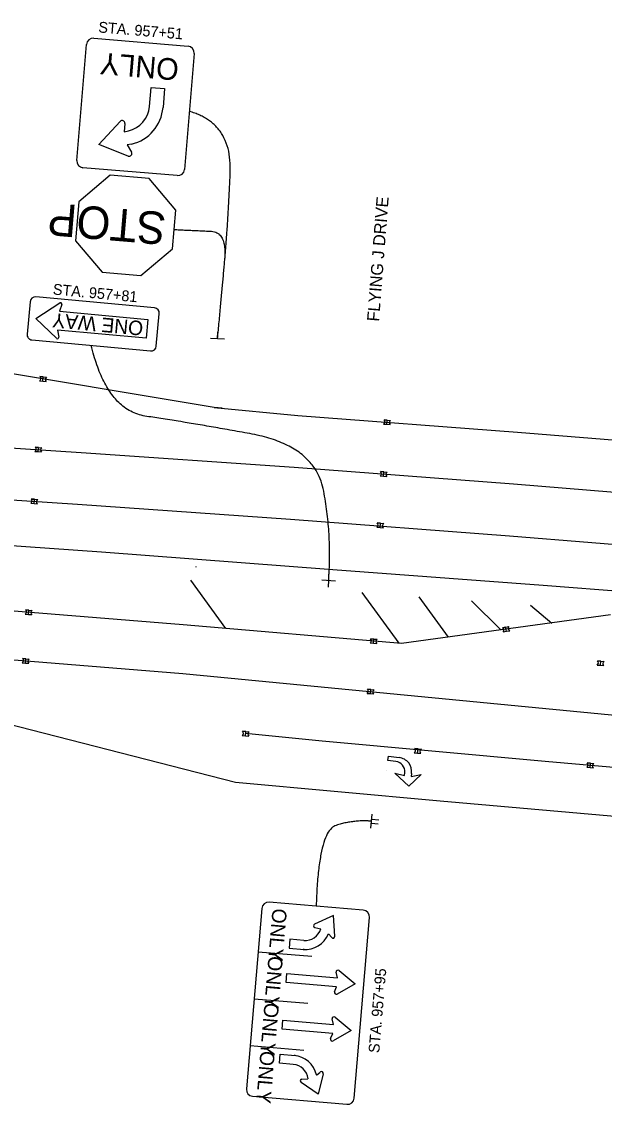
# Model space of a CAD drawing. Extents: x 1847379 to 1850904, y 217032 to 220169.
# Drawn here: x 1849844.7 to 1849979.4, y 218660.5 to 218910.6 of the extents above; entities that cross this region are included whole.
import ezdxf

# ---------------------------------------------------------------- set-up
doc = ezdxf.new("R2010")
doc.units = 0
for name, color, linetype in [('PM_P_Cells', 7, 'Continuous'), ('PM_P_Channelizing_Line', 7, 'Continuous'), ('PM_P_CL_Double_Solid', 7, 'Continuous'), ('PM_P_Edge_Line', 7, 'Continuous'), ('PM_P_Lane_Line', 7, 'Continuous'), ('PM_P_Transverse_Line', 7, 'Continuous'), ('SN_X_Public', 7, 'Continuous'), ('SN_X_Text', 7, 'Continuous')]:
    doc.layers.add(name, color=color, linetype=linetype)

msp = doc.modelspace()

# ---------------------------------------------------------------- linework, layer by layer
at = {"layer": 'PM_P_Cells'}
for p, q in [((1849849.72, 218828.51), (1849848.95, 218828.58)), ((1849848.95, 218828.58), (1849849.72, 218828.51)), ((1849849.63, 218827.54), (1849849.72, 218828.51)), ((1849849.72, 218828.51), (1849850.49, 218828.45)), ((1849848.87, 218827.61), (1849849.63, 218827.54)), ((1849848.87, 218827.61), (1849849.63, 218827.54)), ((1849849.63, 218827.54), (1849850.4, 218827.47)), ((1849929.23, 218818.54), (1849928.47, 218818.61)), ((1849928.47, 218818.61), (1849929.23, 218818.54)), ((1849929.14, 218817.57), (1849929.23, 218818.54)), ((1849929.23, 218818.54), (1849930, 218818.47)), ((1849928.38, 218817.64), (1849929.14, 218817.57)), ((1849928.38, 218817.64), (1849929.14, 218817.57)), ((1849929.14, 218817.57), (1849929.91, 218817.5)), ((1849847.78, 218811.33), (1849848.55, 218811.26)), ((1849847.78, 218811.33), (1849848.55, 218811.26)), ((1849848.63, 218812.23), (1849847.87, 218812.3)), ((1849847.87, 218812.3), (1849848.63, 218812.23)), ((1849848.55, 218811.26), (1849848.63, 218812.23)), ((1849848.55, 218811.26), (1849849.31, 218811.19)), ((1849848.63, 218812.23), (1849849.4, 218812.16)), ((1849927.58, 218805.66), (1849928.35, 218805.6)), ((1849927.58, 218805.66), (1849928.35, 218805.6)), ((1849928.43, 218806.57), (1849927.67, 218806.64)), ((1849927.67, 218806.64), (1849928.43, 218806.57)), ((1849928.35, 218805.6), (1849928.43, 218806.57)), ((1849928.43, 218806.57), (1849929.2, 218806.5)), ((1849928.35, 218805.6), (1849929.11, 218805.53)), ((1849846.81, 218799.34), (1849847.57, 218799.27)), ((1849846.81, 218799.34), (1849847.57, 218799.27)), ((1849847.66, 218800.25), (1849846.89, 218800.32)), ((1849846.89, 218800.32), (1849847.66, 218800.25)), ((1849847.57, 218799.27), (1849847.66, 218800.25)), ((1849847.57, 218799.27), (1849848.34, 218799.21)), ((1849847.66, 218800.25), (1849848.43, 218800.18)), ((1849926.79, 218793.84), (1849927.56, 218793.77)), ((1849926.79, 218793.84), (1849927.56, 218793.77)), ((1849927.64, 218794.74), (1849926.88, 218794.81)), ((1849926.88, 218794.81), (1849927.64, 218794.74)), ((1849927.56, 218793.77), (1849927.64, 218794.74)), ((1849927.56, 218793.77), (1849928.32, 218793.7)), ((1849927.64, 218794.74), (1849928.41, 218794.67)), ((1849845.53, 218773.74), (1849846.29, 218773.68)), ((1849845.53, 218773.74), (1849846.29, 218773.68)), ((1849846.38, 218774.65), (1849845.61, 218774.72)), ((1849845.61, 218774.72), (1849846.38, 218774.65)), ((1849846.29, 218773.68), (1849846.38, 218774.65)), ((1849846.29, 218773.68), (1849847.06, 218773.61)), ((1849846.38, 218774.65), (1849847.15, 218774.58)), ((1849956.59, 218770.72), (1849955.84, 218770.57)), ((1849955.84, 218770.57), (1849956.59, 218770.72)), ((1849956.59, 218770.72), (1849957.35, 218770.87)), ((1849956.78, 218769.76), (1849956.59, 218770.72)), ((1849956.03, 218769.61), (1849956.78, 218769.76)), ((1849956.03, 218769.61), (1849956.78, 218769.76)), ((1849956.78, 218769.76), (1849957.54, 218769.91)), ((1849925.27, 218767.08), (1849926.04, 218767.01)), ((1849925.27, 218767.08), (1849926.04, 218767.01)), ((1849926.12, 218767.98), (1849925.36, 218768.05)), ((1849925.36, 218768.05), (1849926.12, 218767.98)), ((1849926.04, 218767.01), (1849926.12, 218767.98)), ((1849926.04, 218767.01), (1849926.8, 218766.94)), ((1849926.12, 218767.98), (1849926.89, 218767.91)), ((1849845.69, 218763.41), (1849844.92, 218763.48)), ((1849844.92, 218763.48), (1849845.69, 218763.41)), ((1849845.6, 218762.44), (1849845.69, 218763.41)), ((1849845.69, 218763.41), (1849846.46, 218763.34)), ((1849844.84, 218762.51), (1849845.6, 218762.44)), ((1849844.84, 218762.51), (1849845.6, 218762.44)), ((1849845.6, 218762.44), (1849846.37, 218762.37)), ((1849977.71, 218761.98), (1849978.48, 218761.91)), ((1849977.71, 218761.98), (1849978.48, 218761.91)), ((1849978.57, 218762.88), (1849977.8, 218762.95)), ((1849977.8, 218762.95), (1849978.57, 218762.88)), ((1849978.48, 218761.91), (1849978.57, 218762.88)), ((1849978.48, 218761.91), (1849979.25, 218761.84)), ((1849978.57, 218762.88), (1849979.34, 218762.81)), ((1849925.41, 218756.34), (1849924.64, 218756.41)), ((1849924.64, 218756.41), (1849925.41, 218756.34)), ((1849925.32, 218755.37), (1849925.41, 218756.34)), ((1849925.41, 218756.34), (1849926.18, 218756.27)), ((1849924.55, 218755.43), (1849925.32, 218755.37)), ((1849924.55, 218755.43), (1849925.32, 218755.37)), ((1849925.32, 218755.37), (1849926.09, 218755.3)), ((1849895.67, 218745.72), (1849896.44, 218745.65)), ((1849895.67, 218745.72), (1849896.44, 218745.65)), ((1849896.53, 218746.62), (1849895.76, 218746.69)), ((1849895.76, 218746.69), (1849896.53, 218746.62)), ((1849896.44, 218745.65), (1849896.53, 218746.62)), ((1849896.44, 218745.65), (1849897.21, 218745.58)), ((1849896.53, 218746.62), (1849897.3, 218746.55)), ((1849929.38, 218739.89), (1849929.5, 218740.89)), ((1849929.5, 218740.89), (1849931.96, 218740.6)), ((1849935.47, 218741.72), (1849936.24, 218741.65)), ((1849935.47, 218741.72), (1849936.24, 218741.65)), ((1849936.33, 218742.62), (1849935.56, 218742.69)), ((1849935.56, 218742.69), (1849936.33, 218742.62)), ((1849936.24, 218741.65), (1849936.33, 218742.62)), ((1849936.24, 218741.65), (1849937.01, 218741.58)), ((1849936.33, 218742.62), (1849937.1, 218742.55)), ((1849931.24, 218739.68), (1849929.38, 218739.89)), ((1849975.34, 218738.39), (1849976.11, 218738.32)), ((1849975.34, 218738.39), (1849976.11, 218738.32)), ((1849976.19, 218739.29), (1849975.43, 218739.36)), ((1849975.43, 218739.36), (1849976.19, 218739.29)), ((1849976.11, 218738.32), (1849976.19, 218739.29)), ((1849976.11, 218738.32), (1849976.87, 218738.25)), ((1849976.19, 218739.29), (1849976.96, 218739.22)), ((1849929.12, 218737.57), (1849929.12, 218737.57)), ((1849934.18, 218733.97), (1849930.99, 218737.02)), ((1849930.99, 218737.02), (1849933.17, 218736.44)), ((1849933.17, 218736.44), (1849933.26, 218737.14)), ((1849937.07, 218736.66), (1849934.18, 218733.97)), ((1849934.84, 218736.92), (1849934.76, 218736.25)), ((1849934.76, 218736.25), (1849937.07, 218736.66)), ((1849937.07, 218736.66), (1849937.07, 218736.66))]:
    msp.add_line(p, q, dxfattribs=at)
for centre, radius, start, end in [((1849848.61, 218828.13), 0.576, 296.8063, 52.8586), ((1849848.61, 218828.13), 0.576, 296.8063, 52.8586), ((1849850.75, 218827.93), 0.576, 116.8063, 232.8586), ((1849928.12, 218818.15), 0.576, 296.8063, 52.8586), ((1849928.12, 218818.15), 0.576, 296.8063, 52.8586), ((1849930.26, 218817.96), 0.576, 116.8063, 232.8586), ((1849847.52, 218811.84), 0.576, 296.8063, 52.8586), ((1849847.52, 218811.84), 0.576, 296.8063, 52.8586), ((1849849.66, 218811.65), 0.576, 116.8063, 232.8586), ((1849927.32, 218806.18), 0.576, 296.8063, 52.8586), ((1849927.32, 218806.18), 0.576, 296.8063, 52.8586), ((1849929.46, 218805.98), 0.576, 116.8063, 232.8586), ((1849846.55, 218799.86), 0.576, 296.8063, 52.8586), ((1849846.55, 218799.86), 0.576, 296.8063, 52.8586), ((1849848.69, 218799.66), 0.576, 116.8063, 232.8586), ((1849926.53, 218794.35), 0.576, 296.8063, 52.8586), ((1849926.53, 218794.35), 0.576, 296.8063, 52.8586), ((1849928.67, 218794.16), 0.576, 116.8063, 232.8586), ((1849845.27, 218774.26), 0.576, 296.8063, 52.8586), ((1849845.27, 218774.26), 0.576, 296.8063, 52.8586), ((1849847.41, 218774.06), 0.576, 116.8063, 232.8586), ((1849957.74, 218770.45), 0.576, 133.2777, 249.33), ((1849955.63, 218770.03), 0.576, 313.2777, 69.33), ((1849955.63, 218770.03), 0.576, 313.2777, 69.33), ((1849925.01, 218767.59), 0.576, 296.8063, 52.8586), ((1849925.01, 218767.59), 0.576, 296.8063, 52.8586), ((1849927.15, 218767.4), 0.576, 116.8063, 232.8586), ((1849844.58, 218763.02), 0.576, 296.8063, 52.8586), ((1849844.58, 218763.02), 0.576, 296.8063, 52.8586), ((1849846.72, 218762.83), 0.576, 116.8063, 232.8586), ((1849977.45, 218762.49), 0.576, 296.8063, 52.8586), ((1849977.45, 218762.49), 0.576, 296.8063, 52.8586), ((1849979.59, 218762.3), 0.576, 116.8063, 232.8586), ((1849924.29, 218755.95), 0.576, 296.8063, 52.8586), ((1849924.29, 218755.95), 0.576, 296.8063, 52.8586), ((1849926.44, 218755.75), 0.576, 116.8063, 232.8586), ((1849895.41, 218746.23), 0.576, 296.8063, 52.8586), ((1849895.41, 218746.23), 0.576, 296.8063, 52.8586), ((1849897.56, 218746.04), 0.576, 116.8063, 232.8586), ((1849935.21, 218742.23), 0.576, 296.8063, 52.8586), ((1849935.21, 218742.23), 0.576, 296.8063, 52.8586), ((1849937.36, 218742.04), 0.576, 116.8063, 232.8586), ((1849930.97, 218737.4), 2.3, 353.453, 83.453), ((1849931.59, 218737.34), 3.28, 352.5446, 83.453), ((1849975.08, 218738.9), 0.576, 296.8063, 52.8586), ((1849975.08, 218738.9), 0.576, 296.8063, 52.8586), ((1849977.22, 218738.71), 0.576, 116.8063, 232.8586)]:
    msp.add_arc(centre, radius, start, end, dxfattribs=at)
at = {"layer": 'PM_P_Channelizing_Line'}
msp.add_lwpolyline([(1850650.65, 218674.09), (1850566.02, 218682.53), (1850518.02, 218687.39), (1850471.03, 218692.07), (1850419.06, 218697.16), (1850371.65, 218702.19), (1850311.6, 218707.75), (1850264.65, 218712.06), (1850215.84, 218717), (1850171.13, 218721.51), (1850121.19, 218725.85), (1850066.37, 218730.8), (1850014.99, 218735.41), (1849965.69, 218739.72), (1849914.21, 218744.36), (1849896.49, 218746.14)], dxfattribs=at)
at = {"layer": 'PM_P_CL_Double_Solid'}
for p, q in [((1849882.04, 218771.28), (1849831.69, 218775.35)), ((1849980.86, 218773.54), (1849932.52, 218766.94)), ((1849932.52, 218766.94), (1849882.04, 218771.28))]:
    msp.add_line(p, q, dxfattribs=at)
at = {"layer": 'PM_P_Edge_Line'}
for p, q in [((1849815.8, 218791.52), (1849863.14, 218788.13)), ((1849863.14, 218788.13), (1849916.68, 218784.02)), ((1849916.68, 218784.02), (1849965.29, 218780.39)), ((1849965.29, 218780.39), (1850020.28, 218776.15))]:
    msp.add_line(p, q, dxfattribs=at)
for points in [[(1849891.07, 218821.31), (1849889.22, 218821.46), (1849832.32, 218830.92), (1849780.01, 218839.12), (1849775.45, 218839.9), (1849724.32, 218843.71), (1849670.97, 218847.45), (1849610.73, 218851.87), (1849610.54, 218851.85)], [(1849889.22, 218821.46), (1849908.57, 218819.63), (1849959.34, 218815.75), (1850016.54, 218811.11), (1850069.2, 218806.62), (1850120.11, 218802.11), (1850169.53, 218797.86), (1850218.84, 218793.6), (1850268.16, 218788.98), (1850318.46, 218784.1), (1850367.53, 218779.29), (1850417.75, 218774.53), (1850467.84, 218769.49), (1850519.01, 218764.5), (1850567.74, 218759.83), (1850617.52, 218754.84), (1850666.94, 218749.6)], [(1849832.17, 218750.77), (1849894.17, 218734.94), (1849941.43, 218730.63), (1849992.34, 218726.14), (1850039.4, 218721.8), (1850086.44, 218717.54), (1850135.69, 218713.18), (1850171.07, 218709.94)]]:
    msp.add_lwpolyline(points, dxfattribs=at)
at = {"layer": 'PM_P_Lane_Line'}
for p, q in [((1849606.07, 218781.96), (1849881.96, 218760.04)), ((1849881.96, 218760.04), (1850650.78, 218685.87))]:
    msp.add_line(p, q, dxfattribs=at)
for points in [[(1849608.99, 218828.81), (1849660.31, 218825.18), (1849710.18, 218821.58), (1849761.09, 218817.87), (1849808.06, 218814.41), (1849858.45, 218811.1), (1849907.69, 218807.67), (1849958.4, 218803.79), (1850015.55, 218799.15), (1850068.16, 218794.66), (1850119.07, 218790.16), (1850168.5, 218785.91), (1850217.76, 218781.65), (1850267.02, 218777.03), (1850317.3, 218772.15), (1850366.38, 218767.35), (1850416.59, 218762.59), (1850466.65, 218757.55), (1850517.86, 218752.55), (1850566.57, 218747.88), (1850616.29, 218742.91), (1850664.9, 218737.75)], [(1849608.14, 218816.84), (1849659.46, 218813.21), (1849709.31, 218809.62), (1849760.21, 218805.9), (1849807.22, 218802.44), (1849857.63, 218799.12), (1849906.82, 218795.7), (1849957.46, 218791.82), (1850014.55, 218787.19), (1850067.13, 218782.71), (1850118.03, 218778.2), (1850167.47, 218773.95), (1850186.14, 218772.34)]]:
    msp.add_lwpolyline(points, dxfattribs=at)
at = {"layer": 'PM_P_Transverse_Line'}
for p, q in [((1849883.74, 218781.61), (1849891.84, 218770.44)), ((1849923.31, 218778.73), (1849931.88, 218766.99)), ((1849936.5, 218777.74), (1849943.31, 218768.41)), ((1849948.7, 218776.82), (1849955.47, 218770.07)), ((1849962.33, 218775.8), (1849967.24, 218771.68))]:
    msp.add_line(p, q, dxfattribs=at)
at = {"layer": 'SN_X_Public'}
for p, q in [((1849874.28, 218891.02), (1849874.65, 218895.38)), ((1849874.65, 218895.38), (1849877.76, 218895.12)), ((1849877.76, 218895.12), (1849877.4, 218890.76)), ((1849862.57, 218882.18), (1849867.48, 218887.54)), ((1849868.57, 218887.07), (1849868.42, 218885.14)), ((1849868.42, 218885.14), (1849869.39, 218885.36)), ((1849869.34, 218879.53), (1849862.57, 218882.18)), ((1849870.09, 218882.32), (1849869.13, 218882.09)), ((1849869.13, 218882.09), (1849870.11, 218880.43)), ((1849865.19, 218875.1), (1849857.9, 218868.94)), ((1849874.16, 218874.35), (1849865.19, 218875.1)), ((1849880.32, 218867.06), (1849874.16, 218874.35)), ((1849857.9, 218868.94), (1849857.15, 218859.97)), ((1849879.57, 218858.09), (1849880.32, 218867.06)), ((1849857.15, 218859.97), (1849863.31, 218852.68)), ((1849872.28, 218851.93), (1849879.57, 218858.09)), ((1849863.31, 218852.68), (1849872.28, 218851.93)), ((1849847.97, 218842.01), (1849853.52, 218845.61)), ((1849853.99, 218845.25), (1849853.43, 218843.7)), ((1849853.43, 218843.7), (1849873.9, 218841.8)), ((1849852.76, 218837.44), (1849847.97, 218842.01)), ((1849873.9, 218841.8), (1849873.49, 218837.44)), ((1849873.49, 218837.44), (1849853.03, 218839.34)), ((1849853.03, 218839.34), (1849853.29, 218837.71)), ((1849889.99, 218837.31), (1849890.09, 218838.91)), ((1849891.59, 218837.22), (1849888.4, 218837.41)), ((1849884.97, 218784.71), (1849884.95, 218784.54)), ((1849914.07, 218781.69), (1849917.26, 218781.45)), ((1849915.66, 218781.57), (1849915.54, 218779.98)), ((1849925.46, 218724.32), (1849925.74, 218727.51)), ((1849925.6, 218725.91), (1849925.6, 218725.91)), ((1849925.64, 218726.39), (1849927.24, 218726.25)), ((1849925.56, 218725.44), (1849927.15, 218725.29)), ((1849916.79, 218704.15), (1849912.4, 218702.13)), ((1849917.11, 218699.33), (1849916.79, 218704.15)), ((1849912.48, 218701.35), (1849913.84, 218701.02)), ((1849906.71, 218698.63), (1849906.53, 218696.56)), ((1849909.93, 218698.36), (1849906.71, 218698.63)), ((1849915.64, 218699.85), (1849916.38, 218699.02)), ((1849899.36, 218695.76), (1849911.81, 218694.7)), ((1849906.53, 218696.56), (1849910.02, 218696.26)), ((1849910.02, 218696.26), (1849909.75, 218696.28)), ((1849905.86, 218688.67), (1849906.04, 218690.75)), ((1849906.04, 218690.75), (1849917.7, 218689.76)), ((1849917.7, 218689.76), (1849917.42, 218691.01)), ((1849918.09, 218691.43), (1849921.83, 218688.36)), ((1849917.52, 218687.68), (1849905.86, 218688.67)), ((1849921.83, 218688.36), (1849917.63, 218685.97)), ((1849917.03, 218686.49), (1849917.52, 218687.68)), ((1849898.43, 218684.91), (1849910.89, 218683.85)), ((1849917.17, 218680.63), (1849920.91, 218677.57)), ((1849904.95, 218677.87), (1849905.12, 218679.95)), ((1849905.12, 218679.95), (1849916.78, 218678.96)), ((1849916.78, 218678.96), (1849916.5, 218680.22)), ((1849916.61, 218676.89), (1849904.95, 218677.87)), ((1849916.12, 218675.69), (1849916.61, 218676.89)), ((1849920.91, 218677.57), (1849916.71, 218675.17)), ((1849897.51, 218674.06), (1849909.97, 218673)), ((1849904.28, 218669.99), (1849904.45, 218672.06)), ((1849904.45, 218672.06), (1849907.94, 218671.77)), ((1849907.94, 218671.77), (1849907.68, 218671.79)), ((1849907.5, 218669.71), (1849904.28, 218669.99)), ((1849909.51, 218666.34), (1849910.9, 218666.43)), ((1849912.87, 218667.28), (1849913.74, 218667.97)), ((1849914.41, 218667.55), (1849913.29, 218662.85)), ((1849913.29, 218662.85), (1849909.3, 218665.58))]:
    msp.add_line(p, q, dxfattribs=at)
for points in [[(1849861.39, 218906.74), (1849883.18, 218904.91)], [(1849857.45, 218878.53), (1849859.7, 218905.31)], [(1849884.61, 218903.22), (1849882.36, 218876.44)], [(1849880.68, 218875.01), (1849858.88, 218876.84)], [(1849846.66, 218845.9), (1849845.97, 218838.43)], [(1849875.4, 218844.48), (1849848.02, 218847.02)], [(1849875.84, 218835.66), (1849876.53, 218843.12)], [(1849847.1, 218837.07), (1849874.48, 218834.53)], [(1849900.21, 218705.77), (1849896.66, 218664.05)], [(1849923.69, 218705.35), (1849901.89, 218707.2)], [(1849921.57, 218661.93), (1849925.12, 218703.66)], [(1849898.09, 218662.36), (1849919.89, 218660.51)]]:
    msp.add_lwpolyline(points, dxfattribs=at)
for centre, radius, start, end in [((1849861.25, 218905.18), 1.56, 85.207, 175.207), ((1849883.05, 218903.35), 1.56, 355.207, 85.207), ((1849867.95, 218891.55), 6.35, 283.0683, 355.207), ((1849867.95, 218891.55), 9.48, 283.0645, 355.207), ((1849867.95, 218887.11), 0.625, 355.681, 137.4527), ((1849859.01, 218878.4), 1.56, 175.207, 265.207), ((1849869.57, 218880.11), 0.625, 248.6417, 30.4134), ((1849880.81, 218876.57), 1.56, 265.207, 355.207), ((1849847.9, 218845.78), 1.25, 84.6992, 174.6992), ((1849853.69, 218845.35), 0.314, 340.456, 123.0718), ((1849875.29, 218843.24), 1.25, 354.6992, 84.6992), ((1849847.21, 218838.31), 1.25, 174.6992, 264.6992), ((1849852.98, 218837.66), 0.314, 226.3572, 8.9166), ((1849874.59, 218835.77), 1.25, 264.6992, 354.6992), ((1849901.76, 218705.64), 1.56, 85.1482, 175.1482), ((1849923.56, 218703.79), 1.56, 355.1482, 85.1482), ((1849910.25, 218702.1), 3.75, 265.1482, 343.3714), ((1849912.58, 218701.76), 0.417, 114.6554, 256.5335), ((1849910.25, 218702.1), 5.84, 265.1482, 337.3801), ((1849916.69, 218699.3), 0.417, 221.8098, 3.6879), ((1849917.83, 218691.1), 0.417, 50.6319, 192.51), ((1849917.42, 218686.33), 0.417, 157.7863, 299.6644), ((1849916.91, 218680.31), 0.417, 50.6319, 192.51), ((1849916.5, 218675.53), 0.417, 157.7863, 299.6644), ((1849907.18, 218665.98), 5.84, 12.9162, 85.1482), ((1849907.18, 218665.98), 3.75, 6.9249, 85.1482), ((1849909.53, 218665.92), 0.417, 93.7628, 235.6409), ((1849914, 218667.65), 0.417, 346.6084, 128.4865), ((1849898.22, 218663.91), 1.56, 175.1482, 265.1482), ((1849920.02, 218662.06), 1.56, 265.1482, 355.1482)]:
    msp.add_arc(centre, radius, start, end, dxfattribs=at)
at = {"layer": 'SN_X_Text'}
for points in [[(1849889.99, 218837.31), (1849891.21, 218850.09), (1849892.42, 218864.33), (1849893.41, 218887.08), (1849883.49, 218889.83)], [(1849879.95, 218862.58), (1849884.72, 218862.32), (1849892.06, 218862.06), (1849891.65, 218855.97)], [(1849915.66, 218781.57), (1849916.47, 218791.47), (1849912.65, 218812.65), (1849882.66, 218818.1), (1849864.4, 218820.74), (1849860.79, 218835.8)], [(1849925.6, 218725.91), (1849921.34, 218726.23), (1849913.32, 218723.61), (1849912.79, 218706.27)]]:
    msp.add_open_spline(points, degree=2, dxfattribs=at)

# ---------------------------------------------------------------- texts
at = {"layer": 'SN_X_Public'}
for s, height, rotation, p in [('ONLY', 5, 175.207, (1849881.22, 218901.94)), ('STOP', 7.5, 175.207, (1849878.31, 218866.48)), ('FLYING J DRIVE', 2.8, 85.5355, (1849927.32, 218841.24)), ('ONE WAY', 3.333, 174.6992, (1849872.94, 218841.36)), ('ONLY', 3.333, 265.1482, (1849902.72, 218705.85)), ('ONLY', 3.333, 265.1482, (1849901.79, 218694.85)), ('ONLY', 3.333, 265.1482, (1849900.87, 218684.05)), ('ONLY', 3.333, 265.1482, (1849899.93, 218672.95))]:
    msp.add_text(s, height=height, rotation=rotation, dxfattribs=at).set_placement(p)
at = {"layer": 'SN_X_Text'}
for s, rotation, p in [('STA. 957+51', 355.207, (1849862.36, 218908.11)), ('STA. 957+81', 354.6992, (1849851.84, 218847.57)), ('STA. 957+95', 85.1482, (1849927.36, 218672.28))]:
    msp.add_text(s, height=2.5, rotation=rotation, dxfattribs=at).set_placement(p)

doc.saveas('drawing.dxf')
